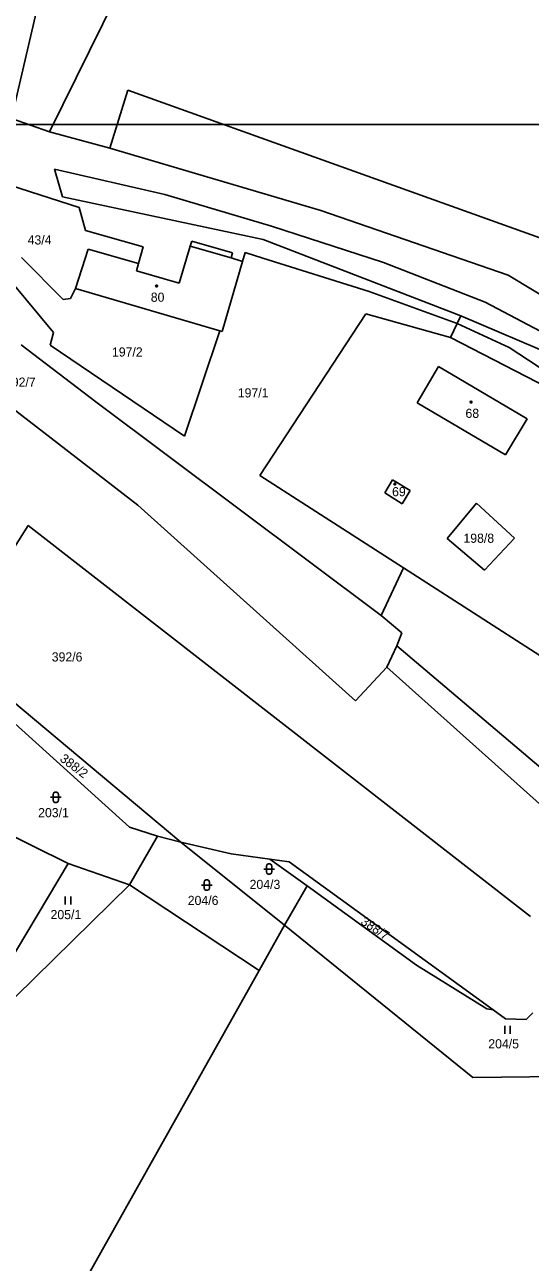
# Model space of a CAD drawing. Extents: x -811039 to -805820, y -1161436 to -1155864.
# Drawn here: x -806386.2 to -806292.6, y -1158211 to -1157981.5 of the extents above; entities that cross this region are included whole.
import ezdxf

# ---------------------------------------------------------------- set-up
doc = ezdxf.new("R2010")
doc.units = 0
for name, color, linetype in [('Default', 7, 'Continuous'), ('Hranice parcel', 7, 'Continuous'), ('ML1000', 7, 'Continuous'), ('Parcelní čísla', 7, 'Continuous'), ('Vnitřní kresba', 7, 'Continuous'), ('Značky budov', 7, 'Continuous'), ('Značky kultur', 7, 'Continuous')]:
    doc.layers.add(name, color=color, linetype=linetype)

# ---------------------------------------------------------------- blocks, each defined once
blk = doc.blocks.new('306')
at = {"layer": 'Default'}
for p, q in [((-0.5, 1.5), (-0.5, 0)), ((0.5, 0), (0.5, 1.5))]:
    blk.add_line(p, q, dxfattribs=at)
blk = doc.blocks.new('316')
at = {"layer": 'Default'}
for points in [[(-1, 1), (0.27, 1), (1, 1)], [(-0.5, 1.5), (-0.4, 1.79), (-0.15, 1.97), (0.16, 1.97), (0.41, 1.79), (0.51, 1.5), (0.51, 0.5), (0.41, 0.21), (0.16, 0.03), (-0.15, 0.03), (-0.4, 0.21), (-0.5, 0.5), (-0.5, 1.5)]]:
    blk.add_lwpolyline(points, dxfattribs=at)
blk = doc.blocks.new('402')
at = {"layer": 'Default'}
blk.add_lwpolyline([(0.09, 0.15), (0.18, 0), (0.09, -0.15), (-0.09, -0.15), (-0.18, 0), (-0.09, 0.15), (0.09, 0.15)], dxfattribs=at)

msp = doc.modelspace()

# ---------------------------------------------------------------- linework, layer by layer
at = {"layer": 'Hranice parcel'}
for p, q in [((-806356.95, -1157951.21), (-806381.62, -1158001.34)), ((-806383.1, -1157974.77), (-806388.68, -1157998.88)), ((-806370.44, -1158004.38), (-806367.13, -1157993.6)), ((-806367.13, -1157993.6), (-806289.91, -1158021.33)), ((-806388.68, -1157998.88), (-806381.62, -1158001.34)), ((-806381.62, -1158001.34), (-806370.44, -1158004.38)), ((-806370.44, -1158004.38), (-806331.33, -1158015.9)), ((-806380.73, -1158008.27), (-806379.23, -1158013.41)), ((-806360.28, -1158012.96), (-806380.73, -1158008.27)), ((-806376.12, -1158015.37), (-806390.69, -1158010.65)), ((-806340.53, -1158018.83), (-806360.28, -1158012.96)), ((-806379.23, -1158013.41), (-806342.05, -1158021.28)), ((-806374.96, -1158019.64), (-806376.12, -1158015.37)), ((-806331.33, -1158015.9), (-806296.62, -1158027.91)), ((-806364.3, -1158022.68), (-806374.96, -1158019.64)), ((-806340.53, -1158018.83), (-806319.73, -1158025.59)), ((-806355.27, -1158021.6), (-806355.56, -1158022.54)), ((-806347.71, -1158023.77), (-806355.27, -1158021.6)), ((-806342.05, -1158021.28), (-806305.43, -1158035.44)), ((-806379.13, -1158032.44), (-806386.8, -1158024.62)), ((-806374.49, -1158023.11), (-806376.79, -1158030.39)), ((-806365.13, -1158025.77), (-806374.49, -1158023.11)), ((-806365.13, -1158025.77), (-806364.3, -1158022.68)), ((-806355.56, -1158022.54), (-806357.59, -1158029.4)), ((-806347.99, -1158024.73), (-806347.71, -1158023.77)), ((-806345.88, -1158025.39), (-806347.99, -1158024.73)), ((-806345.39, -1158023.71), (-806345.88, -1158025.39)), ((-806342.09, -1158024.75), (-806345.39, -1158023.71)), ((-806322.43, -1158030.93), (-806342.09, -1158024.75)), ((-806365.51, -1158027.09), (-806365.13, -1158025.77)), ((-806357.59, -1158029.4), (-806365.51, -1158027.09)), ((-806349.67, -1158038.37), (-806345.88, -1158025.39)), ((-806319.73, -1158025.59), (-806300.91, -1158032.94)), ((-806296.62, -1158027.91), (-806275.48, -1158040.73)), ((-806388.41, -1158029.46), (-806380.92, -1158038.53)), ((-806376.79, -1158030.39), (-806377.73, -1158032.27)), ((-806376.79, -1158030.39), (-806350.05, -1158038.26)), ((-806306.08, -1158036.87), (-806322.43, -1158030.93)), ((-806377.73, -1158032.27), (-806379.13, -1158032.44)), ((-806300.91, -1158032.94), (-806278.74, -1158044.68)), ((-806323.03, -1158035.12), (-806342.67, -1158065.06)), ((-806323.03, -1158035.12), (-806307.33, -1158039.47)), ((-806305.43, -1158035.44), (-806306.08, -1158036.87)), ((-806305.43, -1158035.44), (-806287.42, -1158043.15)), ((-806365.29, -1158070.57), (-806407.54, -1158037.9)), ((-806381.53, -1158040.9), (-806380.92, -1158038.53)), ((-806350.05, -1158038.26), (-806356.63, -1158057.8)), ((-806350.05, -1158038.26), (-806349.67, -1158038.37)), ((-806307.33, -1158039.47), (-806306.08, -1158036.87)), ((-806306.08, -1158036.87), (-806296.48, -1158041.34)), ((-806286.23, -1158050.39), (-806307.33, -1158039.47)), ((-806373.03, -1158051.43), (-806386.86, -1158040.87)), ((-806356.63, -1158057.8), (-806381.53, -1158040.9)), ((-806237, -1158080.46), (-806296.48, -1158041.34)), ((-806313.5, -1158051.6), (-806309.54, -1158044.84)), ((-806309.54, -1158044.84), (-806293.1, -1158054.57)), ((-806373.03, -1158051.43), (-806320.21, -1158091.05)), ((-806297.13, -1158061.26), (-806313.5, -1158051.6)), ((-806293.1, -1158054.57), (-806297.13, -1158061.26)), ((-806316.03, -1158082.21), (-806342.67, -1158065.06)), ((-806319.53, -1158068.32), (-806318.06, -1158065.9)), ((-806318.06, -1158065.9), (-806314.8, -1158067.87)), ((-806316.26, -1158070.31), (-806319.53, -1158068.32)), ((-806314.8, -1158067.87), (-806316.26, -1158070.31)), ((-806324.96, -1158106.89), (-806365.29, -1158070.57)), ((-806307.96, -1158076.73), (-806302.54, -1158070.22)), ((-806302.54, -1158070.22), (-806295.49, -1158076.69)), ((-806391.65, -1158083.89), (-806385.61, -1158074.34)), ((-806292.53, -1158146.89), (-806385.61, -1158074.34)), ((-806301.02, -1158082.62), (-806307.96, -1158076.73)), ((-806295.49, -1158076.69), (-806301.02, -1158082.62)), ((-806320.21, -1158091.05), (-806316.03, -1158082.21)), ((-806233.89, -1158135.1), (-806316.03, -1158082.21)), ((-806316.32, -1158094.25), (-806320.21, -1158091.05)), ((-806317.28, -1158096.64), (-806316.32, -1158094.25)), ((-806319.13, -1158100.62), (-806317.28, -1158096.64)), ((-806253.69, -1158150.72), (-806317.28, -1158096.64)), ((-806319.13, -1158100.62), (-806324.96, -1158106.89)), ((-806319.13, -1158100.62), (-806268.96, -1158145.58)), ((-806357.33, -1158133.11), (-806388.61, -1158106.79)), ((-806366.79, -1158130.31), (-806390, -1158109.34)), ((-806399.36, -1158126.56), (-806378.19, -1158137.05)), ((-806361.6, -1158131.96), (-806366.79, -1158130.31)), ((-806361.6, -1158131.96), (-806366.81, -1158140.98)), ((-806357.33, -1158133.11), (-806361.6, -1158131.96)), ((-806338.08, -1158148.49), (-806357.33, -1158133.11)), ((-806347.97, -1158135.23), (-806357.33, -1158133.11)), ((-806378.19, -1158137.05), (-806394.81, -1158164.93)), ((-806378.19, -1158137.05), (-806366.81, -1158140.98)), ((-806340.83, -1158136.23), (-806347.97, -1158135.23)), ((-806337.24, -1158136.73), (-806340.83, -1158136.23)), ((-806340.83, -1158136.23), (-806333.9, -1158141.2)), ((-806299.41, -1158164.2), (-806337.24, -1158136.73)), ((-806366.81, -1158140.98), (-806393.9, -1158167.57)), ((-806366.81, -1158140.98), (-806342.79, -1158156.88)), ((-806338.08, -1158148.49), (-806333.9, -1158141.2)), ((-806333.9, -1158141.2), (-806313.63, -1158155.9)), ((-806342.79, -1158156.88), (-806338.08, -1158148.49)), ((-806303.18, -1158176.76), (-806338.08, -1158148.49)), ((-806391.51, -1158243.66), (-806342.79, -1158156.88)), ((-806313.63, -1158155.9), (-806300.63, -1158164.02)), ((-806300.63, -1158164.02), (-806299.41, -1158164.2)), ((-806297.16, -1158165.83), (-806299.41, -1158164.2)), ((-806293.29, -1158165.96), (-806292.09, -1158164.72)), ((-806293.29, -1158165.96), (-806297.16, -1158165.83)), ((-806303.18, -1158176.76), (-806271.6, -1158176.32))]:
    msp.add_line(p, q, dxfattribs=at)
at = {"layer": 'ML1000'}
msp.add_lwpolyline([(-806875, -1157000), (-806875, -1158000), (-806250, -1158000), (-806250, -1157000)], close=True, dxfattribs=at)
at = {"layer": 'Vnitřní kresba'}
msp.add_line((-806355.56, -1158022.54), (-806347.99, -1158024.73), dxfattribs=at)

# ---------------------------------------------------------------- block references
at = {"layer": 'Značky budov'}
for p in [(-806361.8, -1158029.94), (-806303.53, -1158051.46), (-806317.65, -1158066.65)]:
    msp.add_blockref('402', p, dxfattribs=at)
at = {"layer": 'Značky kultur'}
for name, p in [('316', (-806380.47, -1158125.76)), ('316', (-806340.94, -1158139.07)), ('316', (-806352.49, -1158142.04)), ('306', (-806378.21, -1158144.66)), ('306', (-806296.75, -1158168.63))]:
    msp.add_blockref(name, p, dxfattribs=at)

# ---------------------------------------------------------------- texts
at = {"layer": 'Parcelní čísla'}
for s, p in [('43/4', (-806385.69, -1158022.23)), ('80', (-806362.87, -1158032.86)), ('197/2', (-806370.06, -1158043.01)), ('392/7', (-806389.89, -1158048.61)), ('197/1', (-806346.75, -1158050.6)), ('68', (-806304.56, -1158054.39)), ('69', (-806318.16, -1158068.92)), ('198/8', (-806304.94, -1158077.56)), ('392/6', (-806381.22, -1158099.57)), ('203/1', (-806383.74, -1158128.46)), ('204/3', (-806344.56, -1158141.77)), ('204/6', (-806356.02, -1158144.74)), ('205/1', (-806381.44, -1158147.36)), ('204/5', (-806300.33, -1158171.33))]:
    msp.add_text(s, height=1.7, dxfattribs=at).set_placement(p)
for s, rotation, p in [('388/2', 323.148, (-806379.86, -1158117.9)), ('388/7', 326.242, (-806324.12, -1158148.17))]:
    msp.add_text(s, height=1.7, rotation=rotation, dxfattribs=at).set_placement(p)

doc.saveas('drawing.dxf')
